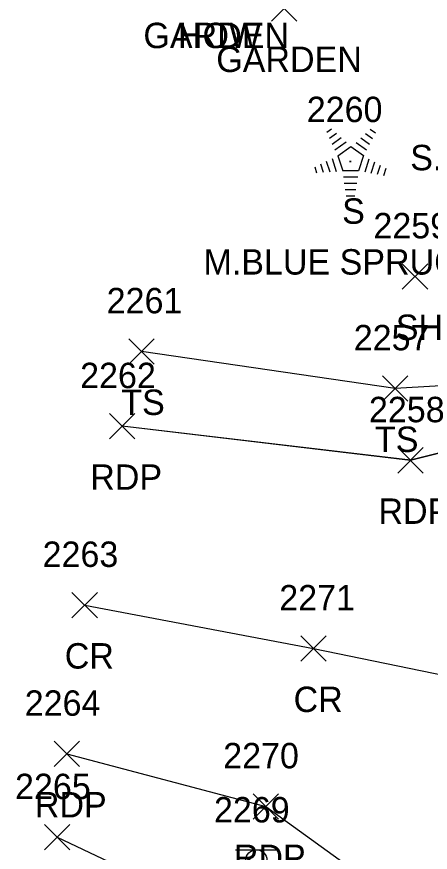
# Model space of a CAD drawing. Extents: x 1554668 to 1563881, y 831386 to 834374.
# Drawn here: x 1562059.1 to 1562091.6, y 831964.7 to 832030.4 of the extents above; entities that cross this region are included whole.
import ezdxf

# ---------------------------------------------------------------- set-up
doc = ezdxf.new("R2010")
doc.units = 0
for name, color, linetype in [('L_A', 7, 'Continuous'), ('L_C', 7, 'Continuous'), ('L_I', 7, 'Continuous'), ('L_TIC', 7, 'Continuous'), ('LELB', 7, 'Continuous'), ('LTC', 7, 'Continuous'), ('P_A', 7, 'Continuous'), ('P_I', 7, 'Continuous'), ('P_TIC', 7, 'Continuous'), ('PET', 7, 'Continuous'), ('PRC', 7, 'Continuous'), ('S_I', 7, 'Continuous'), ('SSGN', 7, 'Continuous')]:
    doc.layers.add(name, color=color, linetype=linetype)

msp = doc.modelspace()

# ---------------------------------------------------------------- linework, layer by layer
at = {"layer": 'L_TIC'}
for points in [[(1562079.089, 832030.089), (1562081.089, 832032.089)], [(1562081.089, 832030.089), (1562079.089, 832032.089)], [(1562089.379, 832008.998), (1562091.379, 832010.998)], [(1562091.379, 832008.998), (1562089.379, 832010.998)], [(1562067.885, 832003.098), (1562069.885, 832005.098)], [(1562069.885, 832003.098), (1562067.885, 832005.098)], [(1562087.823, 832000.185), (1562089.823, 832002.185)], [(1562089.823, 832000.185), (1562087.823, 832002.185)], [(1562061.249, 831964.86), (1562063.249, 831966.86)], [(1562063.249, 831964.86), (1562061.249, 831966.86)]]:
    msp.add_lwpolyline(points, dxfattribs=at)
at = {"layer": 'LELB'}
for points in [[(1562102.727, 832001.986), (1562088.823, 832001.185), (1562068.885, 832004.098)], [(1562102.724, 832001.987), (1562088.821, 832001.186), (1562068.887, 832004.101)], [(1562102.724, 832001.987), (1562088.821, 832001.186), (1562068.887, 832004.101)], [(1562102.724, 832001.987), (1562088.821, 832001.186), (1562068.887, 832004.101)], [(1562062.245, 831965.861), (1562086.96, 831954.13), (1562089.353, 831942.734), (1562087.427, 831930.188), (1562076.841, 831907.606)], [(1562062.245, 831965.861), (1562086.96, 831954.13), (1562089.353, 831942.734), (1562087.427, 831930.188), (1562076.841, 831907.606)], [(1562062.245, 831965.861), (1562086.96, 831954.13), (1562089.353, 831942.734), (1562087.427, 831930.188), (1562076.841, 831907.606)], [(1562062.249, 831965.86), (1562086.964, 831954.131), (1562089.357, 831942.735), (1562087.428, 831930.186), (1562076.842, 831907.602)]]:
    msp.add_lwpolyline(points, dxfattribs=at)
at = {"layer": 'LTC'}
for p, q in [((1562083.46, 832021.354), (1562083.815, 832021.612)), ((1562083.67, 832020.889), (1562084.199, 832021.273)), ((1562086.487, 832021.246), (1562087.037, 832020.847)), ((1562086.858, 832021.595), (1562087.277, 832021.29)), ((1562083.879, 832020.423), (1562084.583, 832020.934)), ((1562084.089, 832019.957), (1562084.967, 832020.595)), ((1562085.745, 832020.55), (1562086.555, 832019.961)), ((1562086.116, 832020.898), (1562086.795, 832020.404)), ((1562084.313, 832019.502), (1562085.325, 832020.237)), ((1562085.325, 832020.237), (1562086.322, 832019.512)), ((1562083.859, 832019.283), (1562084.19, 832018.264)), ((1562084.313, 832019.502), (1562084.7, 832018.309)), ((1562086.322, 832019.512), (1562085.931, 832018.309)), ((1562086.76, 832019.241), (1562086.422, 832018.202)), ((1562082.492, 832018.634), (1562082.645, 832018.166)), ((1562082.948, 832018.85), (1562083.16, 832018.199)), ((1562083.403, 832019.067), (1562083.675, 832018.232)), ((1562087.204, 832018.991), (1562086.917, 832018.106)), ((1562087.649, 832018.741), (1562087.412, 832018.011)), ((1562088.093, 832018.49), (1562087.906, 832017.916)), ((1562085.931, 832018.309), (1562084.7, 832018.309)), ((1562085.892, 832017.809), (1562084.748, 832017.809)), ((1562085.809, 832017.309), (1562084.82, 832017.309)), ((1562085.725, 832016.809), (1562084.893, 832016.809)), ((1562085.641, 832016.309), (1562084.966, 832016.309))]:
    msp.add_line(p, q, dxfattribs=at)
at = {"layer": 'P_TIC'}
for points in [[(1562066.365, 831997.207), (1562068.365, 831999.207)], [(1562068.365, 831997.207), (1562066.365, 831999.207)], [(1562089.016, 831994.525), (1562091.016, 831996.525)], [(1562091.016, 831994.525), (1562089.016, 831996.525)], [(1562063.416, 831983.137), (1562065.416, 831985.137)], [(1562065.416, 831983.137), (1562063.416, 831985.137)], [(1562081.402, 831979.714), (1562083.402, 831981.714)], [(1562083.402, 831979.714), (1562081.402, 831981.714)], [(1562062.012, 831971.421), (1562064.012, 831973.421)], [(1562064.012, 831971.421), (1562062.012, 831973.421)], [(1562077.65, 831967.285), (1562079.65, 831969.285)], [(1562079.65, 831967.285), (1562077.65, 831969.285)]]:
    msp.add_lwpolyline(points, dxfattribs=at)
at = {"layer": 'PET'}
for points in [[(1562118.509, 832011.052), (1562115.548, 832007.554), (1562112.051, 832004.168), (1562107.224, 832001.278), (1562102.857, 831998.75), (1562090.016, 831995.527), (1562067.362, 831998.208)], [(1562118.509, 832011.052), (1562115.548, 832007.554), (1562112.051, 832004.168), (1562107.224, 832001.278), (1562102.857, 831998.75), (1562090.016, 831995.527), (1562067.362, 831998.208)], [(1562118.509, 832011.052), (1562115.548, 832007.554), (1562112.051, 832004.168), (1562107.224, 832001.278), (1562102.857, 831998.75), (1562090.016, 831995.527), (1562067.362, 831998.208)], [(1562118.513, 832011.051), (1562115.552, 832007.555), (1562112.048, 832004.166), (1562107.224, 832001.277), (1562102.854, 831998.747), (1562090.016, 831995.525), (1562067.365, 831998.207)], [(1562063.007, 831972.422), (1562078.649, 831968.287), (1562092.354, 831958.37), (1562094.387, 831954.601), (1562101.44, 831941.076), (1562102.703, 831931.727), (1562102.865, 831928.04)], [(1562063.007, 831972.422), (1562078.649, 831968.287), (1562092.354, 831958.37), (1562094.387, 831954.601), (1562101.44, 831941.076), (1562102.703, 831931.727), (1562102.865, 831928.04)], [(1562063.007, 831972.422), (1562078.649, 831968.287), (1562092.354, 831958.37), (1562094.387, 831954.601), (1562101.44, 831941.076), (1562102.703, 831931.727), (1562102.865, 831928.04)], [(1562063.012, 831972.421), (1562078.65, 831968.285), (1562092.359, 831958.372), (1562094.387, 831954.598), (1562101.443, 831941.076), (1562102.705, 831931.726), (1562102.869, 831928.042)]]:
    msp.add_lwpolyline(points, dxfattribs=at)
at = {"layer": 'PRC'}
for points in [[(1562064.416, 831984.137), (1562082.402, 831980.714), (1562101.256, 831976.837), (1562111.4, 831974.907)], [(1562064.418, 831984.14), (1562082.401, 831980.716), (1562101.253, 831976.837), (1562111.401, 831974.91)], [(1562064.418, 831984.14), (1562082.401, 831980.716), (1562101.253, 831976.837), (1562111.401, 831974.91)], [(1562064.418, 831984.14), (1562082.401, 831980.716), (1562101.253, 831976.837), (1562111.401, 831974.91)]]:
    msp.add_lwpolyline(points, dxfattribs=at)
at = {"layer": 'SSGN'}
msp.add_line((1562076.266, 831964.879), (1562079.599, 831964.879), dxfattribs=at)
msp.add_circle((1562077.912, 831964.046), 0.833, dxfattribs=at)

# ---------------------------------------------------------------- texts
at = {"layer": 'L_A'}
for s, p in [('GARDEN', (1562069.031, 832027.968)), ('HOW', (1562071.747, 832027.968)), ('GARDEN', (1562074.758, 832026.089)), ('S', (1562084.651, 832014.146)), ('SH', (1562088.867, 832004.998)), ('TS', (1562067.294, 831999.098)), ('TS', (1562087.233, 831996.185))]:
    msp.add_text(s, height=2, dxfattribs=at).set_placement(p)
at = {"layer": 'L_C'}
for s, p in [('S.APPLE', (1562090.004, 832018.357)), ('M.BLUE SPRUCE', (1562073.753, 832010.146))]:
    msp.add_text(s, height=2, dxfattribs=at).set_placement(p)
at = {"layer": 'L_I'}
for s, p in [('2260', (1562081.871, 832022.146)), ('2259', (1562087.111, 832012.998)), ('2261', (1562066.145, 832007.098)), ('2257', (1562085.564, 832004.185)), ('2265', (1562058.942, 831968.86))]:
    msp.add_text(s, height=2, dxfattribs=at).set_placement(p)
at = {"layer": 'LTC'}
msp.add_text('.', height=1.037, rotation=270, dxfattribs=at).set_placement((1562085.207, 832019.25))
at = {"layer": 'P_A'}
for s, p in [('RDP', (1562064.853, 831993.207)), ('RDP', (1562087.504, 831990.525)), ('CR', (1562062.849, 831979.137)), ('CR', (1562080.835, 831975.714)), ('RDP', (1562060.5, 831967.421)), ('RDP', (1562076.138, 831963.285))]:
    msp.add_text(s, height=2, dxfattribs=at).set_placement(p)
at = {"layer": 'P_I'}
for s, p in [('2262', (1562064.058, 832001.207)), ('2258', (1562086.756, 831998.525)), ('2263', (1562061.109, 831987.137)), ('2271', (1562079.709, 831983.714)), ('2264', (1562059.705, 831975.421)), ('2270', (1562075.303, 831971.285))]:
    msp.add_text(s, height=2, dxfattribs=at).set_placement(p)
at = {"layer": 'S_I'}
msp.add_text('2269', height=2, dxfattribs=at).set_placement((1562074.578, 831967.026))

doc.saveas('drawing.dxf')
